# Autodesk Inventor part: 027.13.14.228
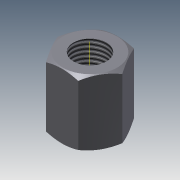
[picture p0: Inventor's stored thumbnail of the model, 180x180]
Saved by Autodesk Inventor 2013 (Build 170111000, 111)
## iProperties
Shininess: 64.0
Length Units: 11269
Angle Units: 11279
Time Units: 11290
Mass Units: 11283
Length Display Precision: 3
Angle Display Precision: 2
Created: 2002-02
Part Number: 027.13.14.228
Material: Steel, Mild
Document SubType Name: Modeling
Designer: SOleg
Density: 7.86 g/cm^3
Density: 0.0
Volumn: 0.0
Area: 0.0
PropertySet Name: Model Information
Control State: 0
Master: False
Checked Out: True
Author: SOleg
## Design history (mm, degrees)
sketch "Sketch1"
  geometry: L1 (9.815, 17)-(19.63, 0); L2 (19.63, 0)-(9.815, -17); L3 (9.815, -17)-(-9.815, -17); L4 (-9.815, -17)-(-19.63, 0); L5 (-19.63, 0)-(-9.815, 17); L6 (-9.815, 17)-(9.815, 17); C1 r 10 at (0, 0); 3 further points
  constraints: 12 end point, 2 coincident, 1 centre point, 1 midpoint, 1 vertical alignment, 13 other
  dimensions: "d1" = 20 diameter of C1
extrude "Extrusion1" new body sketch "Sketch1" distance "d2" = 40; taper "d3" = 0 deg
node "РабОсь1"
sketch "Sketch2"
  geometry: L1 (-16.5, 40)-(-31.416, 40); L2 (0, 45)-(0, -1.383); L3 (-16.5, 40)-(-31.416, 31.388); L4 (-31.416, 31.388)-(-31.416, 40); L5 (17, 0)-(17, 40) reference; L6 (17, 20)-(-24.004, 20); L7 (-16.5, 0)-(-31.416, 0); L8 (-16.5, 0)-(-31.416, 8.612); L9 (-31.416, 8.612)-(-31.416, 0); L10 (0, -10.66)-(0, 54.277) reference; L11 (10, 0)-(-10, 0) reference; L12 (17, 0)-(0, 0) reference; L13 (0, 0)-(-17, 0) reference; L14 (-17, 0)-(0, 0) reference; L15 (0, 0)-(17, 0) reference; L16 (-10, 40)-(10, 40) reference; L17 (17, 40)-(0, 40) reference; L18 (0, 40)-(17, 40) reference; L19 (-17, 40)-(0, 40) reference; L20 (0, 40)-(-17, 40) reference
  constraints: 16 end point, 3 collinear, 3 symmetric about line, 2 perpendicular, 1 midpoint, 3 other
  dimensions: "d5" = 30 deg angle of L1 L3; "d9" = 33 diameter of L7.start L2
revolve "Revolution1" sketch "Sketch2" stored, may be unused: angle "d6" = 90 deg
thread "Thread1" dims "d7" = 10, "d8" = 0
body "Solid1"
node "Спроецированная петля1"
node "Спроецированная петля2"
other parameters: "d0" = 34
